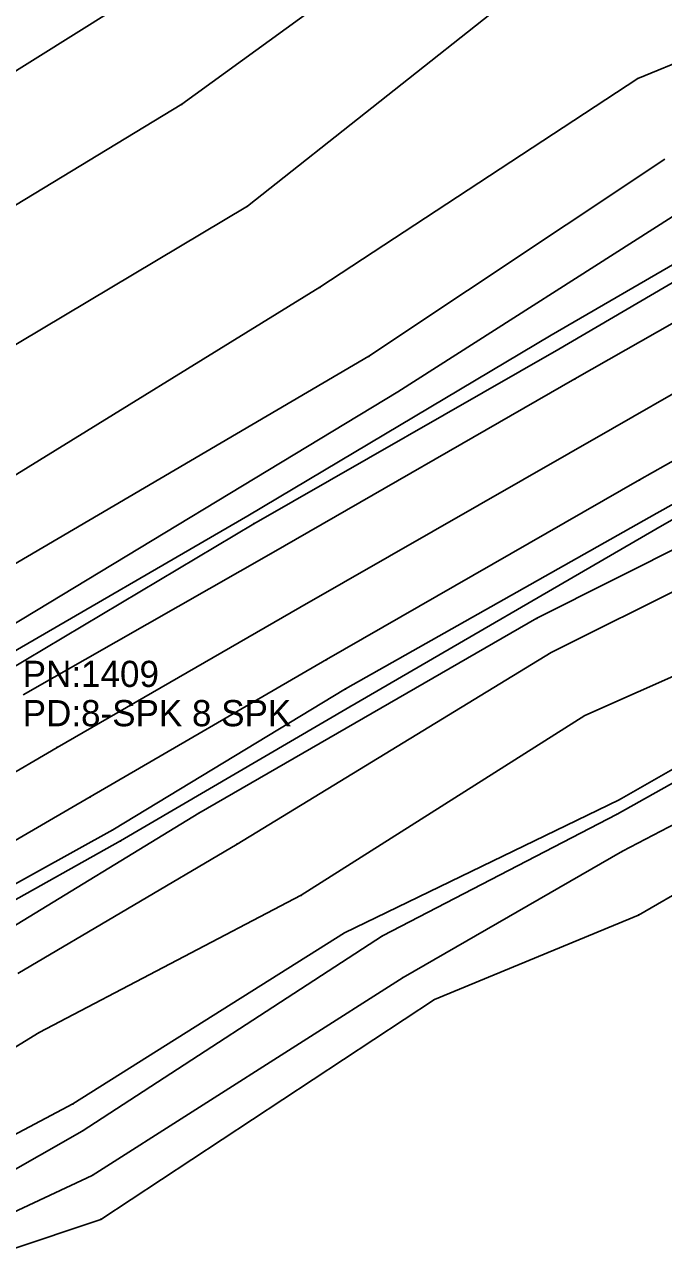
# Model space of a CAD drawing. Extents: x 1419505 to 1434054, y 1956910 to 1968644.
# Drawn here: x 1421225.5 to 1421347.6, y 1957812.6 to 1958046.7 of the extents above; entities that cross this region are included whole.
import ezdxf

# ---------------------------------------------------------------- set-up
doc = ezdxf.new("R2010")
doc.units = 0
for name, color, linetype in [('S_BREAKLINE', 7, 'Continuous'), ('S_DITCHLINE', 7, 'Continuous'), ('S_EDGE_PAVEMENT', 7, 'Continuous'), ('S_GRD_PT_SYM', 7, 'Continuous'), ('S_PAVEMENT_CROWN', 7, 'Continuous'), ('S_RDW_PT_SYM', 7, 'Continuous'), ('S_SECONDARY_CTL_ANNOT', 7, 'Continuous'), ('S_SHOULDER', 7, 'Continuous')]:
    doc.layers.add(name, color=color, linetype=linetype)

msp = doc.modelspace()

# ---------------------------------------------------------------- linework, layer by layer
at = {"layer": 'S_BREAKLINE'}
for p, q in [((1421255.6113, 1958031.4667), (1421313.524, 1958073.6534)), ((1421342.6309, 1958036.386), (1421396.6844, 1958058.5895)), ((1421268.1031, 1958011.9765), (1421326.2938, 1958058.0854)), ((1421174.331, 1958006.9011), (1421242.7334, 1958049.6429)), ((1421281.954, 1957996.5165), (1421342.6309, 1958036.386)), ((1421184.3697, 1957988.2979), (1421255.6113, 1958031.4667)), ((1421291.3056, 1957983.3496), (1421347.8112, 1958020.979)), ((1421195.8474, 1957968.9067), (1421268.1031, 1958011.9765)), ((1421296.8419, 1957976.5532), (1421353.7786, 1958012.8745)), ((1421326.0948, 1957987.3689), (1421369.4216, 1958012.5545)), ((1421207.9522, 1957950.8925), (1421281.954, 1957996.5165)), ((1421268.2021, 1957952.8866), (1421326.0948, 1957987.3689)), ((1421213.4785, 1957937.7117), (1421291.3056, 1957983.3496)), ((1421218.1128, 1957928.9561), (1421296.8419, 1957976.5532)), ((1421347.2972, 1957951.0335), (1421392.7981, 1957976.9622)), ((1421221.039, 1957925.5089), (1421268.2021, 1957952.8866)), ((1421323.3796, 1957933.3114), (1421362.2802, 1957952.8856)), ((1421287.6743, 1957916.4253), (1421347.2972, 1957951.0335)), ((1421326.1278, 1957926.769), (1421368.1135, 1957947.7213)), ((1421332.5282, 1957914.7432), (1421378.4082, 1957935.1425)), ((1421258.8485, 1957896.131), (1421323.3796, 1957933.3114)), ((1421266.1319, 1957890.2106), (1421326.1278, 1957926.769)), ((1421339.0927, 1957898.6621), (1421383.8315, 1957924.2708)), ((1421243.8905, 1957890.7936), (1421287.6743, 1957916.4253)), ((1421278.3957, 1957880.425), (1421332.5282, 1957914.7432)), ((1421342.7579, 1957876.6367), (1421391.7591, 1957904.9155)), ((1421286.6503, 1957873.2455), (1421339.0927, 1957898.6621)), ((1421220.654, 1957872.7775), (1421258.8485, 1957896.131)), ((1421198.4706, 1957865.469), (1421243.8905, 1957890.7936)), ((1421224.2932, 1957865.484), (1421266.1319, 1957890.2106)), ((1421228.3225, 1957854.1883), (1421278.3957, 1957880.425)), ((1421303.8064, 1957860.5147), (1421342.7579, 1957876.6367)), ((1421234.7739, 1957840.5784), (1421286.6503, 1957873.2455)), ((1421240.1033, 1957818.524), (1421303.8064, 1957860.5147)), ((1421171.0408, 1957819.412), (1421228.3225, 1957854.1883)), ((1421187.7319, 1957815.7968), (1421234.7739, 1957840.5784)), ((1421222.4221, 1957812.5936), (1421240.1033, 1957818.524))]:
    msp.add_line(p, q, dxfattribs=at)
at = {"layer": 'S_DITCHLINE'}
for p, q in [((1421338.6796, 1957895.909), (1421384.8616, 1957921.8406)), ((1421339.7237, 1957888.8175), (1421388.2908, 1957914.2671)), ((1421293.8697, 1957872.6495), (1421338.6796, 1957895.909)), ((1421297.818, 1957864.7299), (1421339.7237, 1957888.8175)), ((1421236.555, 1957835.3981), (1421293.8697, 1957872.6495)), ((1421238.4602, 1957826.9395), (1421297.818, 1957864.7299)), ((1421200.1737, 1957814.5957), (1421236.555, 1957835.3981)), ((1421210.9034, 1957813.9817), (1421238.4602, 1957826.9395))]:
    msp.add_line(p, q, dxfattribs=at)
at = {"layer": 'S_EDGE_PAVEMENT'}
for p, q in [((1421330.6481, 1957979.0063), (1421374.812, 1958004.265)), ((1421342.9899, 1957959.7341), (1421386.8237, 1957984.5677)), ((1421272.6184, 1957945.6552), (1421330.6481, 1957979.0063)), ((1421283.222, 1957925.4269), (1421342.9899, 1957959.7341)), ((1421225.2913, 1957918.6664), (1421272.6184, 1957945.6552)), ((1421238.0871, 1957899.1872), (1421283.222, 1957925.4269)), ((1421193.4022, 1957873.3095), (1421238.0871, 1957899.1872))]:
    msp.add_line(p, q, dxfattribs=at)
at = {"layer": 'S_GRD_PT_SYM'}
for points in [[(1421342.6309, 1958036.386), (1421342.6309, 1958036.436), (1421342.6309, 1958036.386), (1421342.5809, 1958036.386), (1421342.6309, 1958036.386), (1421342.6309, 1958036.336), (1421342.6309, 1958036.386), (1421342.6809, 1958036.386)], [(1421255.6113, 1958031.4667), (1421255.6113, 1958031.5167), (1421255.6113, 1958031.4667), (1421255.5613, 1958031.4667), (1421255.6113, 1958031.4667), (1421255.6113, 1958031.4167), (1421255.6113, 1958031.4667), (1421255.6613, 1958031.4667)], [(1421268.1031, 1958011.9765), (1421268.1031, 1958012.0265), (1421268.1031, 1958011.9765), (1421268.0531, 1958011.9765), (1421268.1031, 1958011.9765), (1421268.1031, 1958011.9265), (1421268.1031, 1958011.9765), (1421268.1531, 1958011.9765)], [(1421281.954, 1957996.5165), (1421281.954, 1957996.5665), (1421281.954, 1957996.5165), (1421281.904, 1957996.5165), (1421281.954, 1957996.5165), (1421281.954, 1957996.4665), (1421281.954, 1957996.5165), (1421282.004, 1957996.5165)], [(1421326.0948, 1957987.3689), (1421326.0948, 1957987.4189), (1421326.0948, 1957987.3689), (1421326.0448, 1957987.3689), (1421326.0948, 1957987.3689), (1421326.0948, 1957987.3189), (1421326.0948, 1957987.3689), (1421326.1448, 1957987.3689)], [(1421291.3056, 1957983.3496), (1421291.3056, 1957983.3996), (1421291.3056, 1957983.3496), (1421291.2556, 1957983.3496), (1421291.3056, 1957983.3496), (1421291.3056, 1957983.2996), (1421291.3056, 1957983.3496), (1421291.3556, 1957983.3496)], [(1421296.8419, 1957976.5532), (1421296.8419, 1957976.6032), (1421296.8419, 1957976.5532), (1421296.7919, 1957976.5532), (1421296.8419, 1957976.5532), (1421296.8419, 1957976.5032), (1421296.8419, 1957976.5532), (1421296.8919, 1957976.5532)], [(1421268.2021, 1957952.8866), (1421268.2021, 1957952.9366), (1421268.2021, 1957952.8866), (1421268.1521, 1957952.8866), (1421268.2021, 1957952.8866), (1421268.2021, 1957952.8366), (1421268.2021, 1957952.8866), (1421268.2521, 1957952.8866)], [(1421347.2972, 1957951.0335), (1421347.2972, 1957951.0835), (1421347.2972, 1957951.0335), (1421347.2472, 1957951.0335), (1421347.2972, 1957951.0335), (1421347.2972, 1957950.9835), (1421347.2972, 1957951.0335), (1421347.3472, 1957951.0335)], [(1421323.3796, 1957933.3114), (1421323.3796, 1957933.3614), (1421323.3796, 1957933.3114), (1421323.3296, 1957933.3114), (1421323.3796, 1957933.3114), (1421323.3796, 1957933.2614), (1421323.3796, 1957933.3114), (1421323.4296, 1957933.3114)], [(1421326.1278, 1957926.769), (1421326.1278, 1957926.819), (1421326.1278, 1957926.769), (1421326.0778, 1957926.769), (1421326.1278, 1957926.769), (1421326.1278, 1957926.719), (1421326.1278, 1957926.769), (1421326.1778, 1957926.769)], [(1421287.6743, 1957916.4253), (1421287.6743, 1957916.4753), (1421287.6743, 1957916.4253), (1421287.6243, 1957916.4253), (1421287.6743, 1957916.4253), (1421287.6743, 1957916.3753), (1421287.6743, 1957916.4253), (1421287.7243, 1957916.4253)], [(1421332.5282, 1957914.7432), (1421332.5282, 1957914.7932), (1421332.5282, 1957914.7432), (1421332.4782, 1957914.7432), (1421332.5282, 1957914.7432), (1421332.5282, 1957914.6932), (1421332.5282, 1957914.7432), (1421332.5782, 1957914.7432)], [(1421339.0927, 1957898.6621), (1421339.0927, 1957898.7121), (1421339.0927, 1957898.6621), (1421339.0427, 1957898.6621), (1421339.0927, 1957898.6621), (1421339.0927, 1957898.6121), (1421339.0927, 1957898.6621), (1421339.1427, 1957898.6621)], [(1421258.8485, 1957896.131), (1421258.8485, 1957896.181), (1421258.8485, 1957896.131), (1421258.7985, 1957896.131), (1421258.8485, 1957896.131), (1421258.8485, 1957896.081), (1421258.8485, 1957896.131), (1421258.8985, 1957896.131)], [(1421338.6796, 1957895.909), (1421338.6796, 1957895.959), (1421338.6796, 1957895.909), (1421338.6296, 1957895.909), (1421338.6796, 1957895.909), (1421338.6796, 1957895.859), (1421338.6796, 1957895.909), (1421338.7296, 1957895.909)], [(1421243.8905, 1957890.7936), (1421243.8905, 1957890.8436), (1421243.8905, 1957890.7936), (1421243.8405, 1957890.7936), (1421243.8905, 1957890.7936), (1421243.8905, 1957890.7436), (1421243.8905, 1957890.7936), (1421243.9405, 1957890.7936)], [(1421266.1319, 1957890.2106), (1421266.1319, 1957890.2606), (1421266.1319, 1957890.2106), (1421266.0819, 1957890.2106), (1421266.1319, 1957890.2106), (1421266.1319, 1957890.1606), (1421266.1319, 1957890.2106), (1421266.1819, 1957890.2106)], [(1421339.7237, 1957888.8175), (1421339.7237, 1957888.8675), (1421339.7237, 1957888.8175), (1421339.6737, 1957888.8175), (1421339.7237, 1957888.8175), (1421339.7237, 1957888.7675), (1421339.7237, 1957888.8175), (1421339.7737, 1957888.8175)], [(1421278.3957, 1957880.425), (1421278.3957, 1957880.475), (1421278.3957, 1957880.425), (1421278.3457, 1957880.425), (1421278.3957, 1957880.425), (1421278.3957, 1957880.375), (1421278.3957, 1957880.425), (1421278.4457, 1957880.425)], [(1421342.7579, 1957876.6367), (1421342.7579, 1957876.6867), (1421342.7579, 1957876.6367), (1421342.7079, 1957876.6367), (1421342.7579, 1957876.6367), (1421342.7579, 1957876.5867), (1421342.7579, 1957876.6367), (1421342.8079, 1957876.6367)], [(1421286.6503, 1957873.2455), (1421286.6503, 1957873.2955), (1421286.6503, 1957873.2455), (1421286.6003, 1957873.2455), (1421286.6503, 1957873.2455), (1421286.6503, 1957873.1955), (1421286.6503, 1957873.2455), (1421286.7003, 1957873.2455)], [(1421293.8697, 1957872.6495), (1421293.8697, 1957872.6995), (1421293.8697, 1957872.6495), (1421293.8197, 1957872.6495), (1421293.8697, 1957872.6495), (1421293.8697, 1957872.5995), (1421293.8697, 1957872.6495), (1421293.9197, 1957872.6495)], [(1421297.818, 1957864.7299), (1421297.818, 1957864.7799), (1421297.818, 1957864.7299), (1421297.768, 1957864.7299), (1421297.818, 1957864.7299), (1421297.818, 1957864.6799), (1421297.818, 1957864.7299), (1421297.868, 1957864.7299)], [(1421303.8064, 1957860.5147), (1421303.8064, 1957860.5647), (1421303.8064, 1957860.5147), (1421303.7564, 1957860.5147), (1421303.8064, 1957860.5147), (1421303.8064, 1957860.4647), (1421303.8064, 1957860.5147), (1421303.8564, 1957860.5147)], [(1421228.3225, 1957854.1883), (1421228.3225, 1957854.2383), (1421228.3225, 1957854.1883), (1421228.2725, 1957854.1883), (1421228.3225, 1957854.1883), (1421228.3225, 1957854.1383), (1421228.3225, 1957854.1883), (1421228.3725, 1957854.1883)], [(1421234.7739, 1957840.5784), (1421234.7739, 1957840.6284), (1421234.7739, 1957840.5784), (1421234.7239, 1957840.5784), (1421234.7739, 1957840.5784), (1421234.7739, 1957840.5284), (1421234.7739, 1957840.5784), (1421234.8239, 1957840.5784)], [(1421236.555, 1957835.3981), (1421236.555, 1957835.4481), (1421236.555, 1957835.3981), (1421236.505, 1957835.3981), (1421236.555, 1957835.3981), (1421236.555, 1957835.3481), (1421236.555, 1957835.3981), (1421236.605, 1957835.3981)], [(1421238.4602, 1957826.9395), (1421238.4602, 1957826.9895), (1421238.4602, 1957826.9395), (1421238.4102, 1957826.9395), (1421238.4602, 1957826.9395), (1421238.4602, 1957826.8895), (1421238.4602, 1957826.9395), (1421238.5102, 1957826.9395)], [(1421240.1033, 1957818.524), (1421240.1033, 1957818.574), (1421240.1033, 1957818.524), (1421240.0533, 1957818.524), (1421240.1033, 1957818.524), (1421240.1033, 1957818.474), (1421240.1033, 1957818.524), (1421240.1533, 1957818.524)]]:
    msp.add_lwpolyline(points, dxfattribs=at)
at = {"layer": 'S_PAVEMENT_CROWN'}
for p, q in [((1421337.8446, 1957969.5387), (1421381.2784, 1957994.6743)), ((1421278.1437, 1957935.3755), (1421337.8446, 1957969.5387)), ((1421231.7537, 1957908.6598), (1421278.1437, 1957935.3755)), ((1421188.7099, 1957883.3521), (1421231.7537, 1957908.6598))]:
    msp.add_line(p, q, dxfattribs=at)
at = {"layer": 'S_RDW_PT_SYM'}
for points in [[(1421327.5719, 1957984.6997), (1421327.5719, 1957984.7497), (1421327.5719, 1957984.6997), (1421327.5219, 1957984.6997), (1421327.5719, 1957984.6997), (1421327.5719, 1957984.6497), (1421327.5719, 1957984.6997), (1421327.6219, 1957984.6997)], [(1421330.6481, 1957979.0063), (1421330.6481, 1957979.0563), (1421330.6481, 1957979.0063), (1421330.5981, 1957979.0063), (1421330.6481, 1957979.0063), (1421330.6481, 1957978.9563), (1421330.6481, 1957979.0063), (1421330.6981, 1957979.0063)], [(1421337.8446, 1957969.5387), (1421337.8446, 1957969.5887), (1421337.8446, 1957969.5387), (1421337.7946, 1957969.5387), (1421337.8446, 1957969.5387), (1421337.8446, 1957969.4887), (1421337.8446, 1957969.5387), (1421337.8946, 1957969.5387)], [(1421342.9899, 1957959.7341), (1421342.9899, 1957959.7841), (1421342.9899, 1957959.7341), (1421342.9399, 1957959.7341), (1421342.9899, 1957959.7341), (1421342.9899, 1957959.6841), (1421342.9899, 1957959.7341), (1421343.0399, 1957959.7341)], [(1421346.3101, 1957953.3957), (1421346.3101, 1957953.4457), (1421346.3101, 1957953.3957), (1421346.2601, 1957953.3957), (1421346.3101, 1957953.3957), (1421346.3101, 1957953.3457), (1421346.3101, 1957953.3957), (1421346.3601, 1957953.3957)], [(1421269.3182, 1957951.3645), (1421269.3182, 1957951.4145), (1421269.3182, 1957951.3645), (1421269.2682, 1957951.3645), (1421269.3182, 1957951.3645), (1421269.3182, 1957951.3145), (1421269.3182, 1957951.3645), (1421269.3682, 1957951.3645)], [(1421272.6184, 1957945.6552), (1421272.6184, 1957945.7052), (1421272.6184, 1957945.6552), (1421272.5684, 1957945.6552), (1421272.6184, 1957945.6552), (1421272.6184, 1957945.6052), (1421272.6184, 1957945.6552), (1421272.6684, 1957945.6552)], [(1421278.1437, 1957935.3755), (1421278.1437, 1957935.4255), (1421278.1437, 1957935.3755), (1421278.0937, 1957935.3755), (1421278.1437, 1957935.3755), (1421278.1437, 1957935.3255), (1421278.1437, 1957935.3755), (1421278.1937, 1957935.3755)], [(1421283.222, 1957925.4269), (1421283.222, 1957925.4769), (1421283.222, 1957925.4269), (1421283.172, 1957925.4269), (1421283.222, 1957925.4269), (1421283.222, 1957925.3769), (1421283.222, 1957925.4269), (1421283.272, 1957925.4269)], [(1421286.8353, 1957919.8215), (1421286.8353, 1957919.8715), (1421286.8353, 1957919.8215), (1421286.7853, 1957919.8215), (1421286.8353, 1957919.8215), (1421286.8353, 1957919.7715), (1421286.8353, 1957919.8215), (1421286.8853, 1957919.8215)], [(1421231.7537, 1957908.6598), (1421231.7537, 1957908.7098), (1421231.7537, 1957908.6598), (1421231.7037, 1957908.6598), (1421231.7537, 1957908.6598), (1421231.7537, 1957908.6098), (1421231.7537, 1957908.6598), (1421231.8037, 1957908.6598)], [(1421238.0871, 1957899.1872), (1421238.0871, 1957899.2372), (1421238.0871, 1957899.1872), (1421238.0371, 1957899.1872), (1421238.0871, 1957899.1872), (1421238.0871, 1957899.1372), (1421238.0871, 1957899.1872), (1421238.1371, 1957899.1872)], [(1421242.3844, 1957892.8978), (1421242.3844, 1957892.9478), (1421242.3844, 1957892.8978), (1421242.3344, 1957892.8978), (1421242.3844, 1957892.8978), (1421242.3844, 1957892.8478), (1421242.3844, 1957892.8978), (1421242.4344, 1957892.8978)]]:
    msp.add_lwpolyline(points, dxfattribs=at)
at = {"layer": 'S_SHOULDER'}
for p, q in [((1421327.5719, 1957984.6997), (1421370.9427, 1958010.1213)), ((1421269.3182, 1957951.3645), (1421327.5719, 1957984.6997)), ((1421346.3101, 1957953.3957), (1421390.64, 1957978.4003)), ((1421286.8353, 1957919.8215), (1421346.3101, 1957953.3957)), ((1421222.1831, 1957923.2217), (1421269.3182, 1957951.3645)), ((1421242.3844, 1957892.8978), (1421286.8353, 1957919.8215)), ((1421197.4375, 1957868.0392), (1421242.3844, 1957892.8978))]:
    msp.add_line(p, q, dxfattribs=at)

# ---------------------------------------------------------------- texts
at = {"layer": 'S_SECONDARY_CTL_ANNOT'}
for s, p in [('PN:1409', (1421225.192, 1957920.1969)), ('PD:8-SPK 8 SPK', (1421225.192, 1957912.6969))]:
    msp.add_text(s, height=5, dxfattribs=at).set_placement(p)

doc.saveas('drawing.dxf')
